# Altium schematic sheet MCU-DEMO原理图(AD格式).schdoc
size 283 x 211 mm
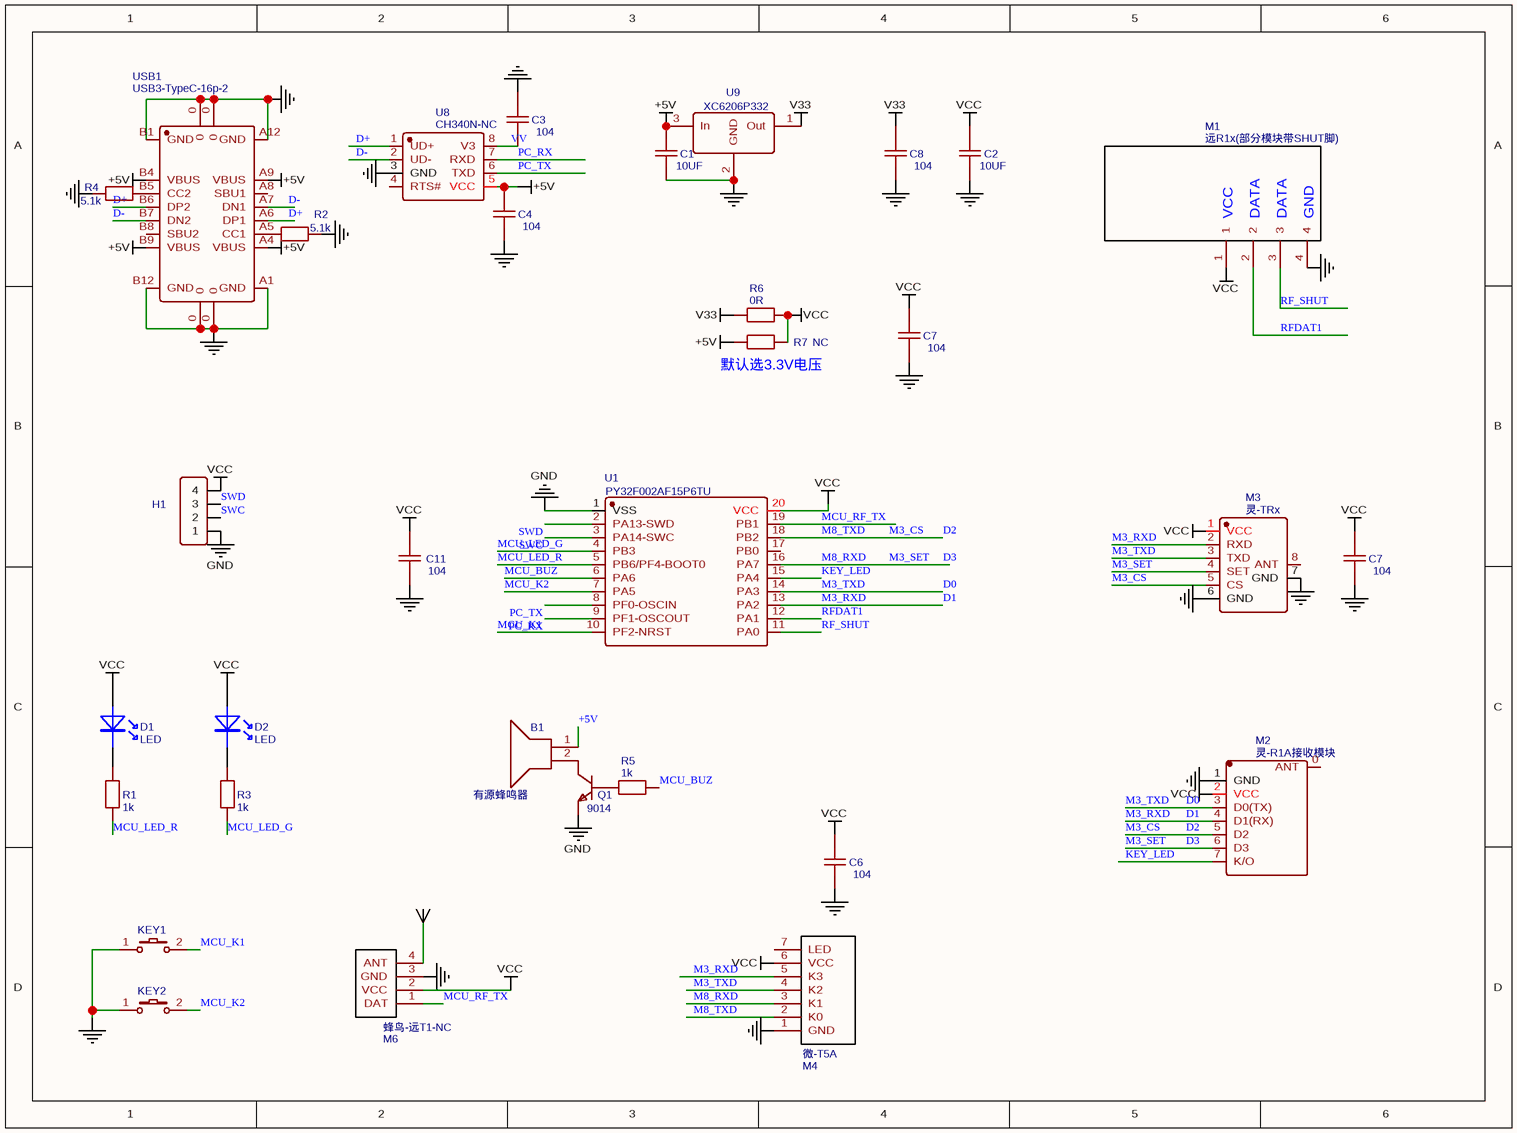
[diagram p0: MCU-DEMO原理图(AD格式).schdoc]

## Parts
(Parts that share a designator on the sheet are numbered #1, #2 ... from top to bottom, then left to right.)
B1  有源蜂鸣器  [BUZ-SMD_L9.6-W9.6-LS10.0-R]
C1  10UF  [C0603]
C2  10UF  [C0603]
C3  104  [R0603/0402]
C4  104  [C0603]
C6  104  [R0603/0402]
C7#1  104  [R0603/0402]
C7#2  104  [R0603/0402]
C8  104  [R0603/0402]
C11  104  [C0603]
D1  LED  [LED0603]
D2  LED  [LED0603]
H1  HDR-F-2.54_1x4  [HDR-F-2.54_1X4]  (value not drawn)
KEY1  K2-3.6×6.1_SMD  [KEY-SMD_2P-L6.2-W3.6-LS8.0]  (value not drawn)
KEY2  K2-3.6×6.1_SMD  [KEY-SMD_2P-L6.2-W3.6-LS8.0]  (value not drawn)
M1  远R1x(部分模块带SHUT脚)  [远R1A_面贴]
M2  灵-R1A接收模块  [灵R1]
M3  灵-TRx  [COMM-SMD_FENGNIAO-LING-TR]
M4  微-T5A  [微-T5A]
M6  蜂鸟-远T1-NC  [蜂鸟-远T1]
Q1  9014  [SOT23]
R1  1k  [R0603/0402]
R2  5.1k  [R0603/0402]
R3  1k  [R0603/0402]
R4  5.1k  [R0603/0402]
R5  1k  [R0603/0402]
R6  0R  [R0603/0402]
R7  NC  [R0603/0402]
U1  PY32F002AF15P6TU  [TSSOP-20_L6.5-W4.4-P0.65-LS6.4-BL]
U8  CH340N-NC  [SOP-8_L5.0-W4.0-P1.27-LS6.0-BL]
U9  XC6206P332  [SOT23]
USB1  USB3-TypeC-16p-2  [USB-TYPE-C_16PIN-MALE-TYPE-C-31-M-12]

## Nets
+5V: B1.1 C1.1 C4.2 R7.2 U8.5(VCC) U9.3(In) USB1.A4(VBUS) USB1.A9(VBUS) USB1.B4(VBUS) USB1.B9(VBUS)
GND: C1.2 C2.1 C3.2 C4.1 C6.1 C7#1.1 C7#2.2 C8.1 C11.1 H1.1 KEY1.1 KEY2.1 M1.4 M2.1(GND) M3.6(GND) M3.7(GND) M4.1(GND) M6.3(GND) Q1.1(E) R2.2 R4.2 U1.1(VSS) U8.3(GND) U9.2(GND) USB1.0 USB1.A1(GND) USB1.A12(GND) USB1.B1(GND) USB1.B12(GND)
V33: C8.2 R6.2 U9.1(Out)
VCC: C2.2 C6.2 C7#1.2 C7#2.1 C11.2 D1.1 D2.1 H1.4 M1.1 M2.2(VCC) M3.1(VCC) M4.6(VCC) M6.2(VCC) R6.1 R7.1 U1.20(VCC)
D0: M2.3(D0(TX)) M3.3(TXD) M4.4(K2) U1.14(PA3)  [also labelled M3_TXD]
D1: M2.4(D1(RX)) M3.2(RXD) M4.5(K3) U1.13(PA2)  [also labelled M3_RXD]
D2: M2.5(D2) M3.5(CS) M4.2(K0) U1.18(PB2)  [also labelled M3_CS, M8_TXD]
D3: M2.6(D3) M3.4(SET) M4.3(K1) U1.16(PA7)  [also labelled M3_SET, M8_RXD]
D+: U8.1(UD+) USB1.A6(DP1) USB1.B6(DP2)
D-: U8.2(UD-) USB1.A7(DN1) USB1.B7(DN2)
KEY_LED: M2.7(K/O) U1.15(PA4)
MCU_BUZ: R5.1 U1.6(PA6)
MCU_K1: KEY1.2 U1.10(PF2-NRST)
MCU_K2: KEY2.2 U1.7(PA5)
MCU_LED_G: R3.2 U1.4(PB3)
MCU_LED_R: R1.2 U1.5(PB6/PF4-BOOT0)
MCU_RF_TX: M6.1(DAT) U1.19(PB1)
PC_RX: U1.9(PF1-OSCOUT) U8.7(RXD)
PC_TX: U1.8(PF0-OSCIN) U8.6(TXD)
RF_SHUT: M1.3 U1.11(PA0)
RFDAT1: M1.2 U1.12(PA1)
SWC: H1.2 U1.3(PA14-SWC)
SWD: H1.3 U1.2(PA13-SWD)
VV: C3.1 U8.8(V3)
NetB1_2: B1.2 Q1.3(C)
NetD1_2: D1.2 R1.1
NetD2_2: D2.2 R3.1
NetQ1_2: Q1.2(B) R5.2
NetR2_1: R2.1 USB1.A5(CC1)
NetR4_1: R4.1 USB1.B5(CC2)

Not connected (* = marked no-connect by the designer): M2 0(ANT); M3 8(ANT); M4 7(LED); M6 4(ANT); U1 17(PB0); U8 4(RTS#); USB1 A8(SBU1) B8(SBU2)

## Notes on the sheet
- (near R7) 默认选3.3V电压

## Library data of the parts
B1 = 有源蜂鸣器: Manufacturer: null; Manufacturer Part: XHZDZ-1207无源蜂鸣器; Contributor: lcsc
C1 C2 = 10UF: nameAlias: Value(F); Contributor: LCEDA_Lib
C3 C4 C6 C7#1 C7#2 C8 C11 = 104: nameAlias: Value(F); Contributor: LCEDA_Lib
D1 D2 = LED: Contributor: leiwei77
H1 = HDR-F-2.54_1x4: Contributor: LCEDA_Lib
KEY1 KEY2 = K2-3.6×6.1_SMD: Manufacturer Part: K2-1107ST-A4SW-06; Contributor: LCEDA_Lib; 制造商: 韩国韩荣
M1 = 远R1x(部分模块带SHUT脚): Contributor: liguichuan
M2 = 灵-R1A接收模块: Manufacturer: Shenzhen LCHSTAR Elec; Contributor: ZEROREZ
M3 = 灵-TRx: Manufacturer: 蜂鸟无线; Manufacturer Part: 灵-TR_433; Contributor: lcsc
M4 = 微-T5A: Contributor: wwulongg
M6 = 蜂鸟-远T1-NC: Contributor: HITLER
Q1 = 9014: Manufacturer: KEC; Manufacturer Part: 2n3904S-RTK/PS; Paste Type: SOT-23; Contributor: LCEDA_Lib
R1 R3 R5 = 1k: nameAlias: Value(Ω); Contributor: LCEDA_Lib
R2 R4 = 5.1k: nameAlias: Value(Ω); Contributor: LCEDA_Lib
R6 = 0R: nameAlias: Value(Ω); Contributor: LCEDA_Lib
R7 = NC: nameAlias: Value(Ω); Contributor: LCEDA_Lib
U1 = PY32F002AF15P6TU: Manufacturer: PUYA(普冉); Contributor: lcsc
U8 = CH340N-NC: Manufacturer: WCH(Jiangsu Qin Heng); Manufacturer Part: CH340N; Contributor: LCSC
U9 = XC6206P332: Contributor: ZimaStraw
USB1 = USB3-TypeC-16p-2: Contributor: jiang082838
